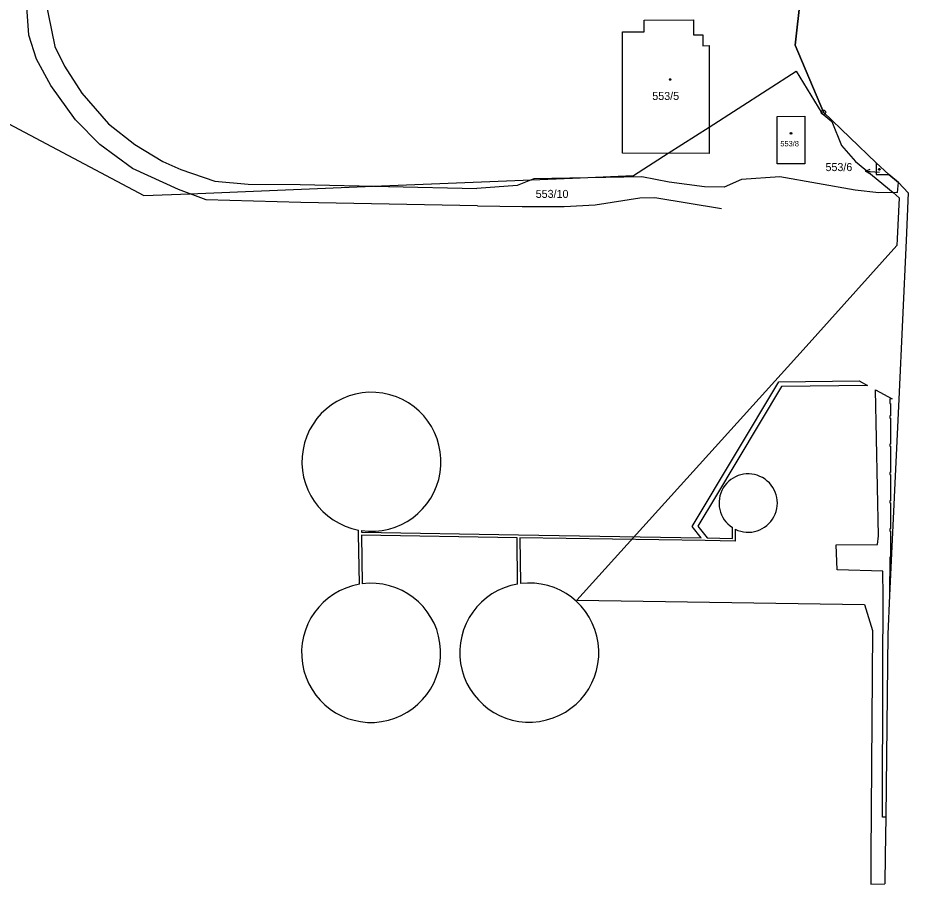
# Model space of a CAD drawing. Extents: x -759699 to -757730, y -1172308 to -1170857.
# Drawn here: x -759085.1 to -758896.1, y -1171950.7 to -1171766.9 of the extents above; entities that cross this region are included whole.
import ezdxf

# ---------------------------------------------------------------- set-up
doc = ezdxf.new("R2010")
doc.units = 0
for name, color, linetype in [('Vrstva 1', 7, 'Continuous'), ('Vrstva 11', 7, 'Continuous'), ('Vrstva 12', 7, 'Continuous'), ('Vrstva 13', 7, 'Continuous'), ('Vrstva 2', 7, 'Continuous'), ('Vrstva 5', 7, 'Continuous'), ('Vrstva 7', 7, 'Continuous'), ('Vrstva 8', 7, 'Continuous')]:
    doc.layers.add(name, color=color, linetype=linetype)

msp = doc.modelspace()

# ---------------------------------------------------------------- linework, layer by layer
at = {"layer": 'Vrstva 1'}
for p, q in [((-758920.09, -1171772.69), (-758918.22, -1171756.06)), ((-759082.76, -1171770.54), (-759083.59, -1171759.79)), ((-759079.99, -1171759.78), (-759077.24, -1171772.97)), ((-758952.15, -1171767.33), (-758941.69, -1171767.31)), ((-758952.15, -1171769.84), (-758952.15, -1171767.33)), ((-758941.69, -1171767.31), (-758941.69, -1171770.44)), ((-759081.13, -1171775.61), (-759082.76, -1171770.54)), ((-758956.77, -1171795.6), (-758956.75, -1171769.86)), ((-758956.75, -1171769.86), (-758952.15, -1171769.84)), ((-758941.69, -1171770.44), (-758939.7, -1171770.44)), ((-758939.7, -1171770.44), (-758939.7, -1171772.81)), ((-759077.24, -1171772.97), (-759075.2, -1171777.12)), ((-758939.7, -1171772.81), (-758938.35, -1171772.74)), ((-758938.35, -1171772.74), (-758938.34, -1171795.62)), ((-758914.11, -1171786.9), (-758920.09, -1171772.69)), ((-759078.11, -1171781.22), (-759081.13, -1171775.61)), ((-759075.2, -1171777.12), (-759071.56, -1171782.86)), ((-759072.9, -1171788.51), (-759078.11, -1171781.22)), ((-759071.56, -1171782.86), (-759065.85, -1171789.32)), ((-758923.93, -1171787.82), (-758918.05, -1171787.74)), ((-758923.92, -1171797.82), (-758923.93, -1171787.82)), ((-758918.05, -1171787.74), (-758918.06, -1171797.81)), ((-758902.91, -1171797.6), (-758914.11, -1171786.9)), ((-759067.75, -1171793.73), (-759072.9, -1171788.51)), ((-759065.85, -1171789.32), (-759060.26, -1171793.74)), ((-759060.8, -1171798.85), (-759067.75, -1171793.73)), ((-759060.26, -1171793.74), (-759054.37, -1171797.38)), ((-758938.34, -1171795.62), (-758956.77, -1171795.6)), ((-759054.37, -1171797.38), (-759050.51, -1171799.07)), ((-758900.25, -1171800.12), (-758902.91, -1171797.6)), ((-758902.91, -1171797.6), (-758902.91, -1171800.12)), ((-759051.03, -1171803.27), (-759060.8, -1171798.85)), ((-759050.51, -1171799.07), (-759043.34, -1171801.5)), ((-758918.06, -1171797.81), (-758923.92, -1171797.82)), ((-759043.34, -1171801.5), (-759036.26, -1171802.13)), ((-758975.57, -1171801.03), (-758979.12, -1171802.46)), ((-758952.69, -1171800.58), (-758975.57, -1171801.03)), ((-758946.89, -1171801.73), (-758952.69, -1171800.58)), ((-758931.49, -1171801.18), (-758935.15, -1171802.79)), ((-758923.34, -1171800.62), (-758931.49, -1171801.18)), ((-758907.39, -1171803.43), (-758923.34, -1171800.62)), ((-758902.91, -1171800.12), (-758900.25, -1171800.12)), ((-758898.18, -1171801.77), (-758900.25, -1171800.12)), ((-759045.13, -1171805.5), (-759051.03, -1171803.27)), ((-759036.26, -1171802.13), (-759025.19, -1171802.26)), ((-759025.19, -1171802.26), (-758987.68, -1171803.06)), ((-758979.12, -1171802.46), (-758987.68, -1171803.06)), ((-758939.33, -1171802.75), (-758946.89, -1171801.73)), ((-758935.15, -1171802.79), (-758939.33, -1171802.75)), ((-758898.38, -1171803.94), (-758898.18, -1171801.77)), ((-758896.12, -1171803.97), (-758898.18, -1171801.77)), ((-758962.54, -1171806.51), (-758953.09, -1171805.07)), ((-758953.09, -1171805.07), (-758949.93, -1171804.98)), ((-758949.93, -1171804.98), (-758935.77, -1171807.34)), ((-758902.37, -1171804), (-758907.39, -1171803.43)), ((-758898.38, -1171803.94), (-758902.37, -1171804)), ((-758896.12, -1171803.97), (-758896.12, -1171803.97)), ((-759025.03, -1171806.02), (-759045.13, -1171805.5)), ((-758987.57, -1171806.72), (-759025.03, -1171806.02)), ((-758987.57, -1171806.72), (-758978.04, -1171806.92)), ((-758978.04, -1171806.92), (-758969.18, -1171806.89)), ((-758969.18, -1171806.89), (-758962.54, -1171806.51)), ((-758935.77, -1171807.34), (-758935.77, -1171807.34))]:
    msp.add_line(p, q, dxfattribs=at)
at = {"layer": 'Vrstva 11'}
for p, q in [((-758918.22, -1171756.06), (-758920.09, -1171772.69)), ((-758920.09, -1171772.69), (-758914.11, -1171786.9)), ((-758938.34, -1171790.03), (-758919.9, -1171778.18)), ((-758919.9, -1171778.18), (-758914.45, -1171787.12)), ((-759090.9, -1171787.36), (-759058.35, -1171804.57)), ((-758914.45, -1171787.12), (-758912.34, -1171788.83)), ((-758914.11, -1171786.9), (-758902.91, -1171797.6)), ((-758947.04, -1171795.61), (-758938.34, -1171790.03)), ((-758912.34, -1171788.83), (-758910.25, -1171793.93)), ((-758910.25, -1171793.93), (-758907.3, -1171797.34)), ((-758954.4, -1171800.34), (-758947.04, -1171795.61)), ((-758907.3, -1171797.34), (-758899.33, -1171803.95)), ((-758902.91, -1171797.6), (-758900.25, -1171800.12)), ((-759009.69, -1171802.59), (-758976.05, -1171801.22)), ((-758976.05, -1171801.22), (-758967.35, -1171800.87)), ((-758967.35, -1171800.87), (-758954.4, -1171800.34)), ((-758900.25, -1171800.12), (-758898.18, -1171801.77)), ((-759048.64, -1171804.18), (-759009.69, -1171802.59)), ((-758898.18, -1171801.77), (-758896.12, -1171803.97)), ((-759058.35, -1171804.57), (-759048.64, -1171804.18)), ((-758899.33, -1171803.95), (-758898.02, -1171805.04)), ((-758898.02, -1171805.04), (-758898.44, -1171813.78)), ((-758896.12, -1171803.97), (-758896.58, -1171814.1)), ((-758898.44, -1171813.78), (-758898.51, -1171815.2)), ((-758896.58, -1171814.1), (-758898.14, -1171847.8)), ((-758898.51, -1171815.2), (-758918.44, -1171837.27)), ((-758918.44, -1171837.27), (-758966.45, -1171890.45)), ((-758898.14, -1171847.8), (-758900.06, -1171889.4)), ((-758900.06, -1171889.4), (-758900.44, -1171897.64)), ((-758966.45, -1171890.45), (-758905.37, -1171891.37)), ((-758905.37, -1171891.37), (-758903.71, -1171896.89)), ((-758903.71, -1171896.89), (-758904.03, -1171944.59)), ((-758900.44, -1171897.64), (-758900.9, -1171936.46)), ((-758900.9, -1171936.46), (-758901, -1171944.59)), ((-758904.03, -1171944.59), (-758904.07, -1171950.68)), ((-758901, -1171944.59), (-758901.07, -1171950.6)), ((-758904.07, -1171950.68), (-758901.07, -1171950.6))]:
    msp.add_line(p, q, dxfattribs=at)
at = {"layer": 'Vrstva 12'}
for p, q in [((-758952.15, -1171767.33), (-758941.69, -1171767.31)), ((-758952.15, -1171769.84), (-758952.15, -1171767.33)), ((-758941.69, -1171767.31), (-758941.69, -1171770.44)), ((-758956.77, -1171795.6), (-758956.75, -1171769.86)), ((-758956.75, -1171769.86), (-758952.15, -1171769.84)), ((-758941.69, -1171770.44), (-758939.7, -1171770.44)), ((-758939.7, -1171770.44), (-758939.7, -1171772.81)), ((-758939.7, -1171772.81), (-758938.35, -1171772.74)), ((-758938.35, -1171772.74), (-758938.34, -1171795.62)), ((-758923.93, -1171787.82), (-758918.05, -1171787.74)), ((-758923.92, -1171797.82), (-758923.93, -1171787.82)), ((-758918.05, -1171787.74), (-758918.06, -1171797.81)), ((-758938.34, -1171795.62), (-758956.77, -1171795.6)), ((-758902.91, -1171797.6), (-758902.91, -1171800.12)), ((-758900.25, -1171800.12), (-758902.91, -1171797.6)), ((-758918.06, -1171797.81), (-758923.92, -1171797.82)), ((-758902.91, -1171800.12), (-758900.25, -1171800.12))]:
    msp.add_line(p, q, dxfattribs=at)
at = {"layer": 'Vrstva 13'}
for p, q in [((-758942.01, -1171874.82), (-758923.6, -1171844.12)), ((-758923.6, -1171844.12), (-758906.52, -1171843.86)), ((-758904.76, -1171844.84), (-758923.04, -1171845.12)), ((-758906.52, -1171843.86), (-758904.76, -1171844.84)), ((-758923.04, -1171845.12), (-758937.01, -1171868.52)), ((-758902.4, -1171876.8), (-758903.03, -1171845.79)), ((-758903.03, -1171845.79), (-758899.54, -1171847.72)), ((-758899.54, -1171847.72), (-758900.02, -1171847.72)), ((-758900.02, -1171847.72), (-758900.02, -1171848.67)), ((-758900.02, -1171848.67), (-758899.87, -1171848.67)), ((-758899.87, -1171848.67), (-758899.87, -1171851.34)), ((-758899.87, -1171851.34), (-758900.02, -1171851.34)), ((-758900.02, -1171851.34), (-758900.02, -1171851.77)), ((-758900.02, -1171851.77), (-758899.87, -1171851.77)), ((-758899.87, -1171851.77), (-758899.88, -1171857.34)), ((-758899.88, -1171857.34), (-758900.03, -1171857.34)), ((-758900.03, -1171857.34), (-758900.03, -1171857.76)), ((-758900.03, -1171857.76), (-758899.88, -1171857.76)), ((-758899.88, -1171857.76), (-758899.89, -1171863.33)), ((-758899.89, -1171863.33), (-758900.03, -1171863.33)), ((-758900.03, -1171863.33), (-758900.03, -1171863.77)), ((-758900.03, -1171863.77), (-758899.89, -1171863.77)), ((-758899.89, -1171863.77), (-758899.89, -1171869.31)), ((-758937.01, -1171868.52), (-758940.79, -1171874.74)), ((-758899.89, -1171869.31), (-758900.04, -1171869.31)), ((-758900.04, -1171869.31), (-758900.04, -1171869.74)), ((-758900.04, -1171869.74), (-758899.89, -1171869.74)), ((-758899.89, -1171869.74), (-758899.9, -1171875.3)), ((-758940.1, -1171877.18), (-758942.01, -1171874.82)), ((-758940.79, -1171874.74), (-758938.81, -1171877.17)), ((-758933.42, -1171877.3), (-758933.43, -1171875.02)), ((-759012.78, -1171876.32), (-759012.78, -1171875.56)), ((-759012.62, -1171887.05), (-759012.78, -1171876.32)), ((-759012.18, -1171875.66), (-759012.18, -1171876.02)), ((-759012.18, -1171876.02), (-758978.82, -1171876.56)), ((-758979.13, -1171877.16), (-759012.18, -1171876.62)), ((-759012.18, -1171876.62), (-759012.02, -1171886.96)), ((-758978.82, -1171876.56), (-758940.1, -1171877.18)), ((-758932.83, -1171875.36), (-758932.82, -1171877.92)), ((-758902.61, -1171878.62), (-758902.4, -1171876.8)), ((-758899.9, -1171875.3), (-758900.05, -1171875.3)), ((-758900.05, -1171875.3), (-758900.05, -1171875.75)), ((-758900.05, -1171875.75), (-758899.9, -1171875.75)), ((-758899.9, -1171875.75), (-758899.9, -1171881.3)), ((-758979.04, -1171886.99), (-758979.13, -1171877.16)), ((-758939.21, -1171877.79), (-758978.53, -1171877.17)), ((-758978.53, -1171877.17), (-758978.44, -1171886.9)), ((-758932.82, -1171877.92), (-758939.21, -1171877.79)), ((-758938.81, -1171877.17), (-758933.42, -1171877.3)), ((-758911.4, -1171878.65), (-758902.61, -1171878.62)), ((-758911.17, -1171883.95), (-758911.4, -1171878.65)), ((-758900.05, -1171881.3), (-758900.06, -1171889.38)), ((-758899.9, -1171881.3), (-758900.05, -1171881.3)), ((-758901.47, -1171884.25), (-758911.17, -1171883.95)), ((-758901.45, -1171889.63), (-758901.47, -1171884.25)), ((-758901.47, -1171905.56), (-758901.45, -1171889.63)), ((-758900.06, -1171889.4), (-758900.44, -1171897.64)), ((-758900.06, -1171889.38), (-758900.06, -1171889.4)), ((-758900.44, -1171897.64), (-758900.9, -1171936.46)), ((-758901.56, -1171936.44), (-758901.47, -1171905.56)), ((-758900.9, -1171936.46), (-758901.56, -1171936.44))]:
    msp.add_line(p, q, dxfattribs=at)
for centre, radius, start, end in [((-759010.055, -1171861.059), 14.755, 261.71878, 259.35657), ((-758930.083, -1171869.813), 6.19, 243.65451, 237.26792), ((-759010.131, -1171901.599), 14.761, 99.70837, 97.35316), ((-758976.551, -1171901.539), 14.761, 99.70837, 97.35316)]:
    msp.add_arc(centre, radius, start, end, dxfattribs=at)
at = {"layer": 'Vrstva 5'}
for points in [[(-758946.56, -1171779.81), (-758946.47, -1171779.96), (-758946.56, -1171780.11), (-758946.74, -1171780.11), (-758946.83, -1171779.96), (-758946.74, -1171779.81)], [(-758920.92, -1171791.22), (-758920.83, -1171791.37), (-758920.92, -1171791.52), (-758921.1, -1171791.52), (-758921.19, -1171791.37), (-758921.1, -1171791.22)], [(-758902.16, -1171798.85), (-758902.07, -1171799), (-758902.16, -1171799.15), (-758902.34, -1171799.15), (-758902.43, -1171799), (-758902.34, -1171798.85)]]:
    msp.add_lwpolyline(points, close=True, dxfattribs=at)
at = {"layer": 'Vrstva 7'}
for p in [(-758905.214, -1171799.383), (-758902.19, -1171799.58)]:
    msp.add_line(p, (-758902.22, -1171799.58), dxfattribs=at)
msp.add_lwpolyline([(-758904.249, -1171799.947), (-758905.214, -1171799.383), (-758904.183, -1171798.95)], dxfattribs=at)
at = {"layer": 'Vrstva 8'}
msp.add_line((-758914.23, -1171786.9), (-758913.99, -1171786.9), dxfattribs=at)
msp.add_lwpolyline([(-758913.96, -1171786.42), (-758913.71, -1171786.6), (-758913.61, -1171786.89), (-758913.71, -1171787.18), (-758913.96, -1171787.36), (-758914.27, -1171787.36), (-758914.52, -1171787.18), (-758914.62, -1171786.89), (-758914.52, -1171786.6), (-758914.27, -1171786.42)], close=True, dxfattribs=at)

# ---------------------------------------------------------------- texts
at = {"layer": 'Vrstva 2'}
for s, height, p in [('553/5', 1.7, (-758950.441, -1171784.29)), ('553/8', 1.14, (-758923.257, -1171794.13)), ('553/6', 0.1, (-758902.403, -1171799.58)), ('553/10', 1.7, (-758975.192, -1171805.07))]:
    msp.add_text(s, height=height, dxfattribs=at).set_placement(p)
at = {"layer": 'Vrstva 7'}
msp.add_text('553/6', height=1.7, dxfattribs=at).set_placement((-758913.676, -1171799.38))

doc.saveas('drawing.dxf')
